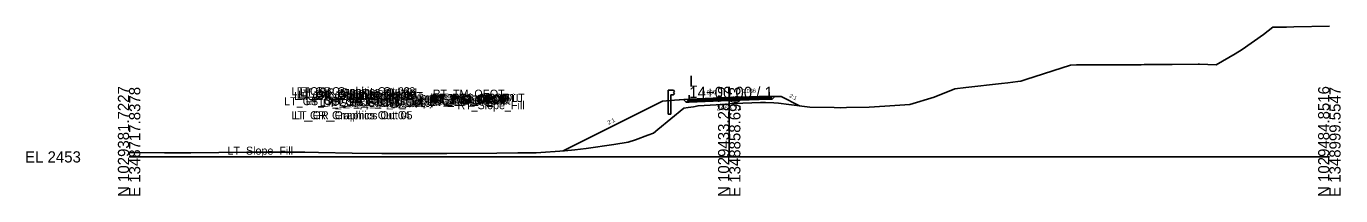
# Model space of a CAD drawing. Extents: x -26 to 1453, y -10 to 4527.
# Drawn here: x -25.7 to 302.8, y 3990.3 to 4032.6 of the extents above; entities that cross this region are included whole.
import ezdxf

# ---------------------------------------------------------------- set-up
doc = ezdxf.new("R2010")
doc.units = 0
for name, color, linetype in [('Default', 7, 'Continuous'), ('Exist Cross Section Cell', 7, 'Continuous'), ('Exist XS Center Line Elevation Label', 7, 'Continuous'), ('Exist XS Ground Line', 7, 'Continuous'), ('Prop CMT Guardrail Graphics', 7, 'Continuous'), ('Prop CMT Pvmt Course 1', 7, 'Continuous'), ('Prop CMT Pvmt Course 2', 7, 'Continuous'), ('Prop CMT Pvmt Course 3', 7, 'Continuous'), ('Prop CMT Pvmt Surface', 7, 'Continuous'), ('Prop CMT Pvmt Surface Overlay', 7, 'Continuous'), ('Prop CMT Pvmt Surface Shoulder', 7, 'Continuous'), ('Prop CMT Shld Paved Course 1', 7, 'Continuous'), ('Prop CMT Shld Paved Course 2', 7, 'Continuous'), ('Prop CMT Shld Paved Course 3', 7, 'Continuous'), ('Prop CMT Slope Grass', 7, 'Continuous'), ('Prop CMT Subgrade Earthwork', 7, 'Continuous'), ('Prop XS Earthwork Shape', 7, 'Continuous'), ('Prop XS EOT Tick Mark', 7, 'Continuous'), ('Prop XS SE Text', 7, 'Continuous'), ('Prop XS Side Slope Text', 7, 'Continuous')]:
    doc.layers.add(name, color=color, linetype=linetype)

msp = doc.modelspace()

# ---------------------------------------------------------------- linework, layer by layer
at = {"layer": 'Exist Cross Section Cell'}
for p, q in [((150, 4000), (150, 4017.52)), ((0, 4000), (150, 4000)), ((150, 4000), (300, 4000))]:
    msp.add_line(p, q, dxfattribs=at)
at = {"layer": 'Exist XS Ground Line'}
msp.add_lwpolyline([(0, 4001.06), (8.85, 4001.02), (15.42, 4000.99), (29.45, 4001.2), (31.08, 4001.21), (31.84, 4001.2), (33.98, 4001.2), (43.91, 4001.15), (47.37, 4001.09), (55.79, 4000.94), (63.15, 4000.88), (78.25, 4000.84), (79.28, 4000.85), (79.42, 4000.85), (91.88, 4000.9), (97.19, 4001), (101.76, 4001.05), (108.81, 4001.53), (111.4, 4001.78), (114.27, 4002.09), (121.14, 4003.1), (124.73, 4003.7), (126.6, 4004.27), (129.67, 4005.43), (131.1, 4005.96), (132.19, 4006.84), (138.69, 4012.15), (139.71, 4012.32), (141.11, 4012.55), (142.21, 4012.77), (149.76, 4013.21), (150, 4013.23), (151.24, 4013.32), (157.82, 4013.56), (159.08, 4013.62), (161.14, 4013.49), (162.33, 4013.41), (164.93, 4013.13), (170.18, 4012.46), (176.25, 4012.33), (177.83, 4012.29), (179.33, 4012.33), (184.98, 4012.45), (188.89, 4012.65), (195.16, 4013.1), (201.24, 4014.9), (206.43, 4017), (209.1, 4017.32), (218.06, 4018.31), (219.64, 4018.52), (222.1, 4018.86), (222.9, 4018.95), (224.13, 4019.34), (235.34, 4022.92), (236.76, 4022.97), (239.05, 4023.02), (251.2, 4023.04), (252.95, 4023.04), (253.69, 4023.05), (260.75, 4023.1), (267.22, 4023.15), (267.52, 4023.14), (271.68, 4023.01), (276.43, 4025.76), (278.21, 4026.86), (283.5, 4030.62), (285.86, 4032.42), (289.29, 4032.43), (291.15, 4032.47), (300, 4032.63)], dxfattribs=at)
at = {"layer": 'Prop CMT Guardrail Graphics'}
for points in [[(134.7, 4010.65), (134.7, 4016.65)], [(134.7, 4016.65), (136.04, 4016.65), (136.31, 4016.36)], [(136.31, 4015.78), (136.04, 4015.48), (135.37, 4015.48)], [(135.37, 4015.48), (135.37, 4010.65)], [(136.31, 4016.36), (136.04, 4016.07)], [(136.04, 4016.07), (136.31, 4015.78)], [(135.37, 4010.65), (134.7, 4010.65)]]:
    msp.add_lwpolyline(points, dxfattribs=at)
at = {"layer": 'Prop CMT Pvmt Course 1'}
for points in [[(150, 4014.8), (140, 4014.45)], [(150, 4014.8), (160, 4015.16)], [(160, 4014.91), (150, 4014.55)], [(150, 4014.68), (150, 4014.8)], [(150, 4014.68), (150, 4014.8)], [(150, 4014.55), (150, 4014.68), (150, 4014.68)], [(150, 4014.55), (150, 4014.68), (150, 4014.68)], [(160, 4015.16), (160, 4014.91)], [(140, 4014.2), (150, 4014.55)], [(140, 4014.45), (140, 4014.2)]]:
    msp.add_lwpolyline(points, dxfattribs=at)
at = {"layer": 'Prop CMT Pvmt Course 2'}
for points in [[(150, 4014.55), (160, 4014.91)], [(160, 4014.91), (160, 4014.66)], [(150, 4014.55), (140, 4014.2)], [(140, 4013.95), (150, 4014.3)], [(140, 4014.2), (140, 4013.95)], [(160, 4014.66), (150, 4014.3)], [(150, 4014.3), (150, 4014.55)], [(150, 4014.3), (150, 4014.55)]]:
    msp.add_lwpolyline(points, dxfattribs=at)
at = {"layer": 'Prop CMT Pvmt Course 3'}
for points in [[(150, 4014.3), (140, 4013.95)], [(140, 4013.7), (150, 4014.05)], [(140, 4013.95), (140, 4013.7)], [(150, 4014.3), (160, 4014.66)], [(160, 4014.41), (150, 4014.05)], [(150, 4014.05), (150, 4014.3)], [(150, 4014.05), (150, 4014.3)], [(160, 4014.66), (160, 4014.41)]]:
    msp.add_lwpolyline(points, dxfattribs=at)
at = {"layer": 'Prop CMT Pvmt Surface'}
for points in [[(150, 4014.8), (140, 4014.45)], [(150, 4014.8), (160, 4015.16)]]:
    msp.add_lwpolyline(points, dxfattribs=at)
at = {"layer": 'Prop CMT Pvmt Surface Overlay'}
for points in [[(150, 4014.8), (140, 4014.45)], [(150, 4014.8), (160, 4015.16)]]:
    msp.add_lwpolyline(points, dxfattribs=at)
at = {"layer": 'Prop CMT Pvmt Surface Shoulder'}
for points in [[(160, 4015.16), (160, 4015.16)], [(140, 4014.45), (140, 4014.45)]]:
    msp.add_lwpolyline(points, dxfattribs=at)
at = {"layer": 'Prop CMT Shld Paved Course 1'}
for points in [[(160, 4015.16), (160, 4015.16), (160.24, 4014.92)], [(160, 4014.91), (160, 4015.16)], [(160.24, 4014.92), (160, 4014.91)], [(140, 4014.45), (140, 4014.45), (139.74, 4014.19)], [(139.74, 4014.19), (140, 4014.2)], [(140, 4014.2), (140, 4014.45)]]:
    msp.add_lwpolyline(points, dxfattribs=at)
at = {"layer": 'Prop CMT Shld Paved Course 2'}
for points in [[(160, 4014.91), (160.24, 4014.92), (160.48, 4014.67)], [(160, 4014.66), (160, 4014.91)], [(160.48, 4014.67), (160, 4014.66)], [(140, 4014.2), (139.74, 4014.19), (139.48, 4013.93)], [(139.48, 4013.93), (140, 4013.95)], [(140, 4013.95), (140, 4014.2)]]:
    msp.add_lwpolyline(points, dxfattribs=at)
at = {"layer": 'Prop CMT Shld Paved Course 3'}
for points in [[(160, 4014.66), (160.48, 4014.67)], [(160.48, 4014.67), (160.48, 4014.67)], [(160.48, 4014.67), (160.73, 4014.43)], [(139.48, 4013.93), (139.22, 4013.67)], [(139.22, 4013.67), (140, 4013.7)], [(140, 4013.95), (139.48, 4013.93)], [(139.48, 4013.93), (139.48, 4013.93)], [(140, 4013.7), (140, 4013.95)], [(160, 4014.41), (160, 4014.66)], [(160.73, 4014.43), (160, 4014.41)]]:
    msp.add_lwpolyline(points, dxfattribs=at)
at = {"layer": 'Prop CMT Slope Grass'}
for points in [[(160, 4015.16), (163, 4015.08)], [(163, 4015.08), (167.58, 4012.79)], [(133.31, 4013.91), (108.51, 4001.51)], [(136.31, 4014.15), (133.31, 4013.91)], [(140, 4014.45), (136.31, 4014.15)]]:
    msp.add_lwpolyline(points, dxfattribs=at)
at = {"layer": 'Prop CMT Subgrade Earthwork'}
for points in [[(160.73, 4014.43), (161.41, 4015.12)], [(139.22, 4013.67), (138.56, 4014.33)], [(140, 4013.7), (139.22, 4013.67)], [(150, 4014.05), (140, 4013.7)], [(150, 4014.05), (160, 4014.41)], [(160, 4014.41), (160.73, 4014.43)]]:
    msp.add_lwpolyline(points, dxfattribs=at)
at = {"layer": 'Prop XS Earthwork Shape'}
msp.add_lwpolyline([(136.31, 4014.15), (133.31, 4013.91), (108.51, 4001.51), (108.81, 4001.53), (111.4, 4001.78), (114.27, 4002.09), (121.14, 4003.1), (124.73, 4003.7), (126.6, 4004.27), (129.67, 4005.43), (131.1, 4005.96), (132.19, 4006.84), (138.69, 4012.15), (139.71, 4012.32), (141.11, 4012.55), (142.21, 4012.77), (149.76, 4013.21), (150, 4013.23), (151.24, 4013.32), (157.82, 4013.56), (159.08, 4013.62), (161.14, 4013.49), (162.33, 4013.41), (164.93, 4013.13), (167.58, 4012.79), (163, 4015.08), (161.41, 4015.12), (160.73, 4014.43), (160, 4014.41), (150, 4014.05), (140, 4013.7), (139.22, 4013.67), (138.56, 4014.33)], close=True, dxfattribs=at)
msp.add_lwpolyline([(136.31, 4014.15), (133.31, 4013.91), (108.51, 4001.51), (108.81, 4001.53), (111.4, 4001.78), (114.27, 4002.09), (121.14, 4003.1), (124.73, 4003.7), (126.6, 4004.27), (129.67, 4005.43), (131.1, 4005.96), (132.19, 4006.84), (138.69, 4012.15), (139.71, 4012.32), (141.11, 4012.55), (142.21, 4012.77), (149.76, 4013.21), (150, 4013.23), (151.24, 4013.32), (157.82, 4013.56), (159.08, 4013.62), (161.14, 4013.49), (162.33, 4013.41), (164.93, 4013.13), (167.58, 4012.79), (163, 4015.08), (161.41, 4015.12), (160.73, 4014.43), (160, 4014.41), (150, 4014.05), (140, 4013.7), (139.22, 4013.67), (138.56, 4014.33)], close=True, dxfattribs=at)
at = {"layer": 'Prop XS EOT Tick Mark'}
for points in [[(140, 4014.45), (140, 4015.45)], [(160, 4015.16), (160, 4016.16)]]:
    msp.add_lwpolyline(points, dxfattribs=at)

# ---------------------------------------------------------------- texts
at = {"layer": 'Default'}
for s, height, p in [('LT_GS_OS_GR_Face_Graphics', 2, (38.77, 4012.91)), ('LT_GR_Graphics Out 03', 2, (40.6, 4015.41)), ('LT_GR_Graphics Out 06', 2, (41.22, 4014.24)), ('LT_GR_Graphics Out 02', 2, (41.94, 4015.41)), ('LT_GR_Graphics Out 09', 2, (41.94, 4014.82)), ('LT_GR_Graphics Out 07', 2, (41.94, 4014.24)), ('LT_GR_Graphics Out 08', 2, (42.21, 4014.53)), ('LT_GR_Graphics Out 01', 2, (42.77, 4015.12)), ('LT_Sub_Trench_Out_DLT', 2, (44.13, 4013.09)), ('LT_GS_OS_CTL', 2, (47.68, 4012.67)), ('LT_PS3_Shelf_Out', 2, (50.47, 4012.69)), ('LT_PS3_OEOP', 2, (54.72, 4012.69)), ('LT_PS2_OEOP', 2, (54.98, 4012.95)), ('LT_PV2_OEOT', 2, (55.17, 4012.95)), ('LT_PV3_OEOT', 2, (55.17, 4012.7)), ('LT_PV1_OEOT', 2, (55.74, 4013.2)), ('LT_PS1_OEOP', 2, (55.8, 4013.2)), ('LT_TM_OEOT', 2, (55.94, 4014.2)), ('RT_PV1_OEEOP_W', 2, (62.94, 4013.38)), ('LT_PV1_OEEOP_W', 2, (62.98, 4013.38)), ('RT_Sub_OEEOP', 2, (64.17, 4012.75)), ('LT_Sub_OEEOP', 2, (64.21, 4012.75)), ('RT_PV2_OEEOP', 2, (64.26, 4013.25)), ('RT_PV3_OEEOP', 2, (64.26, 4013)), ('LT_PV2_OEEOP', 2, (64.31, 4013.25)), ('LT_PV3_OEEOP', 2, (64.31, 4013)), ('RT_Sub_Trench_Out_DLT', 2, (66.93, 4013.76)), ('PV1_PGL_W', 2, (67.58, 4013.38)), ('PV1_PGL', 2, (69.47, 4013.5)), ('RT_Sub_Trench_Out', 2, (69.89, 4013.07)), ('RT_PS3_Shelf_Out', 2, (71.42, 4013.32)), ('RT_Sub_OEOT', 2, (75.03, 4013.05)), ('RT_PV2_OEOT', 2, (75.13, 4013.55)), ('RT_PV3_OEOT', 2, (75.13, 4013.3)), ('RT_PS2_OEOP', 2, (75.43, 4013.56)), ('RT_PS3_OEOP', 2, (75.68, 4013.32)), ('RT_PV1_OEOT', 2, (75.69, 4013.8)), ('RT_PS1_OEOP', 2, (75.76, 4013.8)), ('RT_TM_OEOT', 2, (75.9, 4014.8)), ('RT_GS_OS_CTL', 2, (77.32, 4013.71)), ('LT_GR_Graphics Out 04', 2, (40.6, 4009.41)), ('LT_GR_Graphics Out 05', 2, (41.27, 4009.41)), ('LT_Sub_Trench_Out', 2, (48.43, 4012.43)), ('LT_Sub_OEOT', 2, (55.08, 4012.45)), ('RT_Slope_Fill', 2, (82.06, 4011.92)), ('LT_Slope_Fill', 2, (24.61, 4000.56)), ('-', 0.0001, (0, 4000)), ('-', 0.0001, (0, 4000)), ('-', 0.0001, (0, 4000)), ('-', 0.0001, (0, 4000))]:
    msp.add_text(s, height=height, dxfattribs=at).set_placement(p)
at = {"layer": 'Exist Cross Section Cell'}
for s, p in [('L', (140, 4017.52)), ('14+00.00 / 1', (140, 4014.72)), ('EL 2453', (-26, 3998.6))]:
    msp.add_text(s, height=2.8, dxfattribs=at).set_placement(p)
for s, p in [('N 1029381.7227', (0, 3990)), ('E 1348717.8378', (2.8, 3990)), ('N 1029433.2872', (150, 3990)), ('E 1348858.6963', (152.8, 3990)), ('N 1029484.8516', (300, 3990)), ('E 1348999.5547', (302.8, 3990))]:
    msp.add_text(s, height=2.8, rotation=90, dxfattribs=at).set_placement(p)
at = {"layer": 'Exist XS Center Line Elevation Label'}
msp.add_text('2466.23', height=1.23, dxfattribs=at).set_placement((146.87, 4011.61))
at = {"layer": 'Prop XS SE Text'}
for p in [(143.23, 4015.56), (153.23, 4015.92)]:
    msp.add_text('0.036', height=1, rotation=2.036, dxfattribs=at).set_placement(p)
at = {"layer": 'Prop XS Side Slope Text'}
for rotation, p in [(333.4349, (164.92, 4014.96)), (26.5651, (119.87, 4008.03))]:
    msp.add_text('2:1', height=1, rotation=rotation, dxfattribs=at).set_placement(p)

doc.saveas('drawing.dxf')
